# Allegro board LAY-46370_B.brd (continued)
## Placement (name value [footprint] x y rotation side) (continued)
R328  22  [0402_CC]  15.29 10.84 90 top
R329  10K  [0402_CC]  16.83 13.45 90 top
R330  12K  [0402_CC]  12.22 13.11 270 top
R333  1.5K  [0402_CC]  21.49 21.94 180 top
R334  1.5K  [0402_CC]  21.49 23.5 180 top
R347  10K  [0402_CC]  6.98 52.18 90 bottom
R351  10K  [0402_CC]  24.01 67.24 180 bottom
R363  0  [0402_CC]  7.02 64.89 0 bottom
R364  0  [0402_CC]  7.02 65.98 0 bottom
R369  0  [0402_CC]  156.01 86.88 270 bottom
R370  0  [0402_CC]  154.92 86.88 270 bottom
R371  0  [0402_CC]  153.83 86.88 270 bottom
R372  0  [0402_CC]  152.74 86.88 270 bottom
R373  1K  [0402_CC]  163.3 83.55 270 bottom
R374  1K  [0402_CC]  160.87 83.48 270 bottom
R381  1K  [0402_CC]  21.33 52.93 90 bottom
R382  0  [0402_CC]  22.3 47.06 180 bottom
R383  10K  [0402_CC]  22.31 48.23 180 bottom
R385  10K  [0402_CC]  19.25 52.94 90 bottom
R386  100  [0402_CC]  9.13 73.62 90 bottom
R387  100  [0402_CC]  10.23 73.63 90 bottom
R388  100  [0402_CC]  11.34 73.63 90 bottom
R389  100  [0402_CC]  12.47 73.63 90 bottom
R390  100  [0402_CC]  13.57 73.61 90 bottom
R391  100  [0402_CC]  14.66 73.6 90 bottom
R392  100  [0402_CC]  15.76 73.6 90 bottom
R393  100  [0402_CC]  15.97 71.96 0 bottom
R394  100  [0402_CC]  15.97 70.87 0 bottom
R395  100  [0402_CC]  15.97 69.76 0 bottom
R396  100  [0402_CC]  15.98 67.55 0 bottom
R397  100  [0402_CC]  15.19 64.62 270 bottom
R398  100  [0402_CC]  14.11 64.62 270 bottom
R399  100  [0402_CC]  10.85 64.62 270 bottom
R400  100  [0402_CC]  9.76 64.62 270 bottom
R401  100  [0402_CC]  33.96 65.57 270 top
R406  0  [0402_CC]  12.31 133.65 270 top
R407  0  [0402_CC]  177.98 87.32 0 top
R408  0  [0402_CC]  21.02 68.92 270 bottom
R409  10K  [0402_CC]  22.15 68.92 270 bottom
R410  10K  [0402_CC]  19.92 68.9 270 bottom
R411  10K  [0402_CC]  8.06 73.62 270 bottom
R412  0  [0402_CC]  6.97 73.61 270 bottom
R413  10K  [0402_CC]  7.05 69.46 0 bottom
R415  10K  [0402_CC]  15.97 68.65 180 bottom
R416  10K  [0402_CC]  15.97 66.46 180 bottom
R417  10K  [0402_CC]  16.27 64.62 90 bottom
R418  10K  [0402_CC]  13.02 64.62 90 bottom
R419  10K  [0402_CC]  11.94 64.62 90 bottom
R420  10K  [0402_CC]  8.67 64.62 90 bottom
R421  10K  [0402_CC]  35.11 65.55 90 top
R422  0  [RC0402_25]  151.67 86.88 270 bottom
R423  0  [RC0402_25]  150.69 86.88 270 bottom
R424  0  [RC0402_25]  87.96 24.57 0 top
R425  0  [RC0402_25]  87.96 26.67 0 top
R426  10K  [0402_CC]  130.5 23.86 90 top
R427  10K  [0402_CC]  13.15 79.47 0 bottom
R429  10K  [0402_CC]  15.01 39.13 270 top
R430  10K  [0402_CC]  13.92 39.13 270 top
R431  10K  [0402_CC]  18.88 31.7 90 top
R435  0  [0402_CC]  13.38 33.02 90 top
R436  0  [RC0402_25]  23.93 73.29 90 bottom
R437  0  [RC0402_25]  22.82 73.28 90 bottom
R438  4.7K  [0402_CC]  91.16 34.32 90 top
R439  4.7K  [0402_CC]  78.08 36.58 270 top
R440  0  [0402_CC]  25.21 54.29 270 bottom
R441  0  [0402_CC]  29.68 47.3 90 bottom
R442  0  [0402_CC]  28.61 47.29 90 bottom
R443  0  [0402_CC]  27.55 47.29 90 bottom
R444  10K  [0402_CC]  178.79 85.29 180 top
R445  10K  [0402_CC]  178.78 84.2 180 top
R446  0  [0402_CC]  19.03 102.2 180 bottom
R447  10K  [0402_CC]  28.77 18.2 180 top
R448  10K  [0402_CC]  56.68 25.49 270 top
R449  0  [0402_CC]  5.4 67.63 90 bottom
R450  100K  [0402_CC]  17.38 98.34 180 bottom
R451  22K  [0402_CC]  126.63 80.1 0 bottom
R452  0  [0402_CC]  133.13 76.2 0 bottom
R453  47K  [0603_CC]  32.32 15.15 180 bottom
R455  10K  [0402_CC]  176.71 125.54 0 top
R456  0  [0402_CC]  179.78 119.73 180 top
R457  10K  [0402_CC]  179.78 120.89 0 top
R458  0  [RC0402_25]  19.86 75.08 270 bottom
SW1  SPST PB  [SW4_PB_ESW_SM_P177]  193.16 145.98 180 top
SW2  SPST PB  [SW4_PB_ESW_SM_P177]  180.17 146 180 top
SW3  M096H-A020RT21A  [SW6_DPDT_M096H_TH]  19.56 145.1 180 top
SW4  DHN-04  [97C04]  7.01 130 0 top
TP1  TP_35MIL  [TESTPOINT_35MIL]  110.23 116.55 0 top
TP2  TP_35MIL  [TESTPOINT_35MIL]  111.75 116.55 0 top
TP3  TP_35MIL  [TESTPOINT_35MIL]  113.28 116.55 0 top
TP4  TP_35MIL  [TESTPOINT_35MIL]  114.8 116.55 0 top
TP5  TP_35MIL  [TESTPOINT_35MIL]  174.53 102.7 0 top
TP6  TP_35MIL  [TESTPOINT_35MIL]  174.53 101.31 0 top
TP7  TP_35MIL  [TESTPOINT_35MIL]  174.53 99.91 0 top
TP8  TP_35MIL  [TESTPOINT_35MIL]  174.53 98.51 0 top
TP9  TP_35MIL  [TESTPOINT_35MIL]  111.21 87.09 270 bottom
TP10  TP_35MIL  [TESTPOINT_35MIL]  108.59 87.05 270 bottom
TP11  TP_35MIL  [TESTPOINT_35MIL]  113.01 84.15 90 bottom
TP12  TP_35MIL  [TESTPOINT_35MIL]  110.07 82.45 90 bottom
TP13  -  [TPAD_020]  25.51 27.47 90 top
TP14  -  [TPAD_020]  29.71 10.02 90 top
TP15  -  [TPAD_020]  35.81 3.52 0 top
TP16  -  [TPAD_020]  27.24 14.8 270 top
TP17  -  [TPAD_020]  33.23 15.23 180 top
TP18  -  [TPAD_020]  28.77 21.03 180 top
TP19  -  [TPAD_020]  28.73 14.8 180 top
TP20  -  [TPAD_020]  33.35 21.49 180 top
TP21  -  [TPAD_020]  29.98 14.8 180 top
TP22  TP_35MIL  [TESTPOINT_35MIL]  28.78 19.61 180 top
TP23  TP_35MIL  [TESTPOINT_35MIL]  45.14 22.22 270 top
TP24  -  [TPAD_020]  45.88 9.5 0 top
TP25  -  [TPAD_020]  38.29 3.52 0 top
TP26  -  [TPAD_020]  42.74 14.43 0 top
TP27  -  [TPAD_020]  43.45 29.44 180 top
TP28  -  [TPAD_020]  41.7 24.4 180 top
TP29  -  [TPAD_020]  45.74 29.44 180 top
TP30  -  [TPAD_020]  43.51 24.39 180 top
TP31  TP_35MIL  [TESTPOINT_35MIL]  41.91 28.81 180 top
TP32  TP_35MIL  [TESTPOINT_35MIL]  109.75 34.02 0 top
TP33  -  [TPAD_020]  97.23 29.24 0 top
TP34  TP_35MIL  [TESTPOINT_35MIL]  77.44 38.25 0 top
TP35  -  [TPAD_020]  78.26 28.56 0 top
TP36  -  [TPAD_020]  163.92 110.15 180 top
TP37  -  [TPAD_020]  163.54 99.61 0 top
TP38  -  [TPAD_020]  162.5 99.59 0 top
TP39  -  [TPAD_020]  150.57 89.82 0 top
TP40  -  [TPAD_020]  149.2 127.96 0 top
TP41  -  [TPAD_050]  178.76 130.83 0 top
TP42  TP_35MIL  [TESTPOINT_35MIL]  105.98 66.72 90 bottom
TP43  -  [TPAD_050]  62.94 135.12 180 bottom
TP44  -  [TPAD_050]  86.25 135.09 180 bottom
TP45  -  [TPAD_020]  78.38 114.89 270 top
TP46  -  [TPAD_020]  79.69 114.88 0 top
TP47  -  [TPAD_050]  38.56 134.87 180 bottom
TP48  -  [TPAD_020]  36.51 134.83 180 bottom
TP49  -  [TPAD_020]  133.2 132.3 180 bottom
TP50  -  [TPAD_020]  108.88 132.77 180 bottom
TP51  -  [TPAD_020]  192.98 26.2 180 top
TP52  -  [TPAD_020]  98.45 54.15 0 top
TP53  -  [TPAD_020]  99.72 54.15 0 top
TP54  -  [TPAD_020]  101 54.15 0 top
TP55  -  [TPAD_020]  102.27 54.15 0 top
TP56  TP_35MIL  [TESTPOINT_35MIL]  104.1 66.73 270 bottom
TP57  TP_35MIL  [TESTPOINT_35MIL]  13.38 41.07 0 top
TP58  TP_35MIL  [TESTPOINT_35MIL]  10.33 41.07 0 top
TP60  TP_35MIL  [TESTPOINT_35MIL]  11.86 41.07 0 top
TP61  TP_35MIL  [TESTPOINT_35MIL]  8.81 41.07 0 top
TP62  -  [TPAD_020]  117.67 79.67 0 top
TP67  -  [TPAD_050]  181.98 112.14 180 top
TP68  -  [TPAD_050]  188.84 112.14 180 top
TP69  TP_35MIL  [TESTPOINT_35MIL]  46.64 65.74 180 bottom
TP70  -  [TPAD_050]  185.41 112.14 0 top
TP71  TP_35MIL  [TESTPOINT_35MIL]  45.09 104.46 270 bottom
TP72  TESTLOOP  [TEST_PIN_TP107]  150.09 20.63 0 top
TP73  TESTLOOP  [TEST_PIN_TP107]  38.66 37.74 0 top
TP74  TESTLOOP  [TEST_PIN_TP107]  7.12 88.3 180 bottom
TP75  -  [TPAD_050]  175.7 130.77 0 top
TP76  -  [TPAD_050]  107.66 116.51 0 top
TP77  -  [TPAD_050]  176.84 52.98 0 top
TP78  -  [TPAD_050]  113.06 24.42 0 top
TP79  -  [TPAD_050]  116.78 116.6 0 top
TP80  -  [TPAD_050]  93.56 40.6 0 top
TP81  TP_35MIL  [TESTPOINT_35MIL]  19.03 100.94 0 bottom
TP82  TP_35MIL  [TESTPOINT_35MIL]  125.64 58.12 180 top
TP83  TP_35MIL  [TESTPOINT_35MIL]  125.64 59.64 180 top
TP84  TP_35MIL  [TESTPOINT_35MIL]  125.64 61.17 180 top
TP85  TP_35MIL  [TESTPOINT_35MIL]  125.64 56.59 180 top
TP86  TP_35MIL  [TESTPOINT_35MIL]  178.69 50.8 0 top
TP87  -  [TPAD_020]  159.86 133.1 0 top
TP88  -  [TPAD_020]  161.21 133.12 0 top
TP89  TP_35MIL  [TESTPOINT_35MIL]  161.61 127.94 0 top
TP90  TP_35MIL  [TESTPOINT_35MIL]  161.84 123.78 0 top
TP93  -  [TPAD_020]  4.77 20.93 0 top
TP94  -  [TPAD_020]  160.02 135.95 0 top
TP95  -  [TPAD_020]  161.29 135.95 0 top
TP96  -  [TPAD_020]  21.29 70.25 180 bottom
TP97  -  [TPAD_020]  33.61 16.2 0 top
TP98  -  [TPAD_020]  152.78 95.91 0 top
TP99  TP_35MIL  [TESTPOINT_35MIL]  138.8 86.68 90 top
TP100  TP_35MIL  [TESTPOINT_35MIL]  138.8 85.28 90 top
TP101  TP_35MIL  [TESTPOINT_35MIL]  138.8 83.88 90 top
TP102  -  [TPAD_050]  32.71 30.09 0 top
TP103  TP_35MIL  [TESTPOINT_35MIL]  55.95 18.08 0 top
TP104  TP_35MIL  [TESTPOINT_35MIL]  143.56 87.2 0 top
TP105  -  [TPAD_050]  23.54 121.92 0 top
TP106  TP_35MIL  [TESTPOINT_35MIL]  133.88 41.44 0 top
TP107  TP_35MIL  [TESTPOINT_35MIL]  130.07 41.44 0 top
TP108  TP_35MIL  [TESTPOINT_35MIL]  131.98 41.44 0 top
TP109  TP_35MIL  [TESTPOINT_35MIL]  128.17 41.44 0 top
TP110  -  [TPAD_050]  56.55 35.57 0 top
TP111  TP_35MIL  [TESTPOINT_35MIL]  44.33 126.03 0 top
TP112  TP_35MIL  [TESTPOINT_35MIL]  68.3 126.1 0 top
TP113  TP_35MIL  [TESTPOINT_35MIL]  92.24 126.03 0 top
TP114  TP_35MIL  [TESTPOINT_35MIL]  116.35 126.09 0 top
TP115  TP_35MIL  [TESTPOINT_35MIL]  140.35 126.03 0 top
TP116  TP_35MIL  [TESTPOINT_35MIL]  157.32 84.47 0 top
TP117  TP_35MIL  [TESTPOINT_35MIL]  155.42 84.47 0 top
TP118  TP_35MIL  [TESTPOINT_35MIL]  153.51 84.47 0 top
TP119  TP_35MIL  [TESTPOINT_35MIL]  151.61 84.47 0 top
TP120  -  [TPAD_050]  197.95 138.42 0 top
TP121  -  [TPAD_050]  96.5 54.2 0 top
TP122  -  [TPAD_050]  84.17 115.48 0 top
TP123  -  [TPAD_050]  86.21 115.48 0 top
TP124  -  [TPAD_020]  20.71 35 0 top
TP125  TP_35MIL  [TESTPOINT_35MIL]  172.27 123.23 0 top
TP126  TP_35MIL  [TESTPOINT_35MIL]  24.81 47.68 270 bottom
TP127  TP_35MIL  [TESTPOINT_35MIL]  22.65 64.38 270 bottom
TP128  -  [TPAD_020]  159.06 105.29 0 top
TP129  TP_35MIL  [TESTPOINT_35MIL]  28.32 41.19 0 top
TP130  TP_35MIL  [TESTPOINT_35MIL]  29.97 41.19 0 top
TP131  TP_35MIL  [TESTPOINT_35MIL]  91.05 54.24 0 top
TP132  TP_35MIL  [TESTPOINT_35MIL]  92.7 54.24 0 top
TP133  -  [TPAD_020]  21.12 19.07 0 top
TP134  -  [TPAD_020]  23.55 69.28 180 bottom
TVS1  ESD5B5.0ST1G  [DIODE2_SOD523]  175.69 133.5 90 bottom
TVS2  ESD5B5.0ST1G  [DIODE2_SOD523]  180.36 133.47 90 bottom
TVS3  ESD5B5.0ST1G  [DIODE2_SOD523]  198.94 15.52 270 top
TVS4  ESD5B5.0ST1G  [DIODE2_SOD523]  190.02 15.58 270 top
TVS5  ESD5B5.0ST1G  [DIODE2_SOD523]  192.92 15.6 270 top
TVS6  ESD5B5.0ST1G  [DIODE2_SOD523]  196.03 15.5 270 top
TVS7  ESD5B5.0ST1G  [DIODE2_SOD523]  12.04 7.95 270 top
TVS8  ESD5B5.0ST1G  [DIODE2_SOD523]  35.19 70.1 270 bottom
U1  PCA6416AHF,128  [QFN24_4X4_EP2P25MM]  182.4 85.22 270 top
U2  74LVC1G125GM  [UDFN6_1X1P5MM]  177.94 89.02 0 top
U3  74AVC8T245BQ  [QFN24_0P5_5P6X3P6_EP]  133.74 86.18 0 bottom
U4  74AVC4T245GU  [XQFN16_0P4_2P7X1P9]  117.93 32.38 0 top
U5  NTS0104GU12  [XQFN12_0P4_1P8X2P1]  179.92 101.29 0 top
U6  NTS0104GU12  [XQFN12_0P4_1P8X2P1]  111.63 93.75 270 bottom
U7  74AVC4T3144  [XQFN12_0P4_1P8X2P1]  14.11 49.14 180 bottom
U8  TMUX1574RSVR  [PQFN16_0P4_2P65X1P85]  8.23 49.37 270 bottom
U9  NX20P5090UK  [WLCSP15_0P5_1P57X2P59]  29.59 25.19 90 top
U10  NX20P0407  [WLCSP12_0P4_1P3X1P7MM_SMDP]  26.01 12.34 90 top
U11  PTN5110  [HX2QFN16_0P4_2P7X2P7]  32.19 18.32 180 top
U12  SGM8709YN5G  [SOT-23-5]  68.36 36.75 0 top
U13  TPS70933DBVR  [SOT23-5]  42.48 19.69 270 top
U14  NX20P3483UK  [WLCSP42_0P4_2P94X2P54_SMDP]  59.13 33.95 180 top
U15  NX20P0407  [WLCSP12_0P4_1P3X1P7MM_SMDP]  41.94 12.39 90 top
U16  PCMF2USB3S  [WLCSP10_0P4_1P2X1P6MM_SMDP]  46.43 12.43 270 top
U17  PTN5110  [HX2QFN16_0P4_2P7X2P7]  44.87 26.73 180 top
U18  CBTU02043  [HUQFN16_1P6X2P4]  49.32 17.05 270 top
U19  PCMF2USB3S  [WLCSP10_0P4_1P2X1P6MM_SMDP]  49.4 12.38 270 top
U20  TMUX1574RSVR  [PQFN16_0P4_2P65X1P85]  9.77 78.17 180 bottom
U21  PCMF2USB3S  [WLCSP10_0P4_1P2X1P6MM_SMDP]  67.66 20.61 270 top
U22  NX5P3363UKZ  [BGA16_0P5_2P23X2P23]  59.08 22.75 90 top
U23  RTL8211FDI-CG  [QFN40_0P4_5X5MM]  101.62 28.66 90 top
U24  IP4292CZ10-TBR  [XSON10_0P5_1P1X2P6MM]  104.82 19.96 90 top
U25  IP4292CZ10-TBR  [XSON10_0P5_1P1X2P6MM]  100.81 19.96 90 top
U26  RTL8211FDI-CG  [QFN40_0P4_5X5MM]  82.56 28.69 90 top
U27  IP4292CZ10-TBR  [XSON10_0P5_1P1X2P6MM]  84.46 19.96 90 top
U28  IP4292CZ10-TBR  [XSON10_0P5_1P1X2P6MM]  80.43 19.96 90 top
U29  9FGV0241AKLF  [QFN24_0P5_4X4_EP2P2]  159.95 109.84 180 top
U30  PCMF1HDMI2S  [WLCSP5_0P4_0P82X1P22]  160.33 137.56 0 top
U31  IP4292CZ10-TBR  [XSON10_0P5_1P1X2P6MM]  70.86 126.08 90 top
U32  IP4292CZ10-TBR  [XSON10_0P5_1P1X2P6MM]  65.77 126.08 270 top
U33  IP4292CZ10-TBR  [XSON10_0P5_1P1X2P6MM]  57.14 126.08 270 top
U34  IP4292CZ10-TBR  [XSON10_0P5_1P1X2P6MM]  94.73 126.08 90 top
U35  IP4292CZ10-TBR  [XSON10_0P5_1P1X2P6MM]  89.71 126.08 270 top
U36  IP4292CZ10-TBR  [XSON10_0P5_1P1X2P6MM]  80.8 126.08 270 top
U37  IP4292CZ10-TBR  [XSON10_0P5_1P1X2P6MM]  41.87 126.08 270 top
U38  IP4292CZ10-TBR  [XSON10_0P5_1P1X2P6MM]  46.82 126.08 90 top
U39  IP4292CZ10-TBR  [XSON10_0P5_1P1X2P6MM]  32.61 126.08 270 top
U40  IP4292CZ10-TBR  [XSON10_0P5_1P1X2P6MM]  142.89 126.08 90 top
U41  IP4292CZ10-TBR  [XSON10_0P5_1P1X2P6MM]  137.84 126.08 270 top
U42  IP4292CZ10-TBR  [XSON10_0P5_1P1X2P6MM]  129.09 126.08 270 top
U43  IP4292CZ10-TBR  [XSON10_0P5_1P1X2P6MM]  118.87 126.08 90 top
U44  IP4292CZ10-TBR  [XSON10_0P5_1P1X2P6MM]  113.72 126.08 270 top
U45  IP4292CZ10-TBR  [XSON10_0P5_1P1X2P6MM]  105.25 126.08 270 top
U46  PCMF2HDMI2S  [WLCSP10_0P4_1P2X1P6MM_SMDP]  158.08 137.55 90 top
U47  PCMF2HDMI2S  [WLCSP10_0P4_1P2X1P6MM_SMDP]  155.68 137.56 90 top
U48  PCA9509ADP  [TSSOP8_A]  167.74 126.22 0 top
U49  MP2263GD  [DFN15_0P4_2X3]  22.83 99.31 90 bottom
U50  WM8960  [QFN32_S142EP]  191.96 30.07 180 top
U51  TJA1048T  [SOIC14_1P27_4X8]  134.6 28.89 270 top
U52  NLAS3158  [WDFN12_0P5_3X1MM]  110.32 84.52 90 bottom
U53  74AVC4T245GU  [XQFN16_0P4_2P7X1P9]  134.94 37.94 90 top
U54  NLAS3158  [WDFN12_0P5_3X1MM]  130.81 57.54 90 top
U55  NTB0104GU12  [XQFN12_0P4_1P8X2P1]  182.59 75.77 0 top
U56  NTS0104GU12  [XQFN12_0P4_1P8X2P1]  182.64 93.69 0 top
U57  NTB0104GU12  [XQFN12_0P4_1P8X2P1]  182.42 58.01 0 top
U58  NTB0104GU12  [XQFN12_0P4_1P8X2P1]  182.45 49.49 0 top
U59  RT9193  [SOT23-5]  3.9 13.08 0 top
U60  FT4232H  [LQFP64_0P5_10X10]  13.02 21.45 90 top
U61  74AVC4T245GU  [XQFN16_0P4_2P7X1P9]  12.4 36.47 90 top
U62  PCMF1USB3S  [WLCSP5_0P4_0P82X1P22]  14.74 8.67 180 top
U63  MP8759GD  [QFN12_0P5_3P1X2P1]  42.91 64.79 180 bottom
U64  MP2147GD  [QFN12_0P5_2X3MM_EP]  41.65 106.61 270 bottom
U66  74AUP1G126GM  [UDFN6_1X1P5MM]  21.21 73.16 270 bottom
U67  74AUP1G126GM  [UDFN6_1X1P5MM]  21.78 66.58 270 bottom
U70  PCA6416AHF,128  [QFN24_4X4_EP2P25MM]  11.41 69.07 0 bottom
U71  AP2331SA-7  [SOT-23]  171.09 138.23 270 top
U74  RT9193-18GB  [SOT23-5]  5.14 31.12 0 top
U75  PCMF1USB3S  [WLCSP5_0P4_0P82X1P22]  44.36 12.43 180 top
U77  PCMF1USB3S  [WLCSP5_0P4_0P82X1P22]  65.44 20.6 180 top
U78  74LVC1G04GM  [UDFN6_1X1P5MM]  17.25 31.71 90 top
U79  74LVC1G125GM  [UDFN6_1X1P5MM]  162.32 130.77 270 top
U80  AT24C16C  [TSSOP8]  27.87 52.5 270 bottom
U81  74LVC1G125GM  [UDFN6_1X1P5MM]  155.91 103.28 180 top
X1  12 MHz  [XTAL_4_3P3X2P6MM]  8.31 11.23 0 top
Y1  25MHz  [XTLOSC4_2P5X2MM_SM]  94.97 26.73 270 top
Y2  25MHz  [XTLOSC4_2P5X2MM_SM]  75.75 25.42 270 top
Y3  25MHz  [XTLOSC4_2P5X2MM_SM]  166.46 108.29 90 top

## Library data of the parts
BH1-BH4 BH9-BH12 = MOUNT_HOLE
BH5-BH8 = SPACER
C1 C3 C6 C8 C14 C34 C48 C50 C52 C53 C55 C68 C75 C84 C87 C94 C104 C168 C223 C238 C263 C277 C283 C286 C288 C305 C307 C309 C317 C319 C321 C324 C328 C330 C333 C334 = CAP_NP: tolerance: 10%
C2 C4 C5 C7 C9-C13 C15-C24 C27 C29-C33 C35-C37 C42-C47 C51 C54 C56 C57 C59 C60 C64-C67 C69-C74 C76-C78 C85 C86 C88-C93 C95 C96 C112 C115 C123-C137 C139 C140 C143 C144 C147-C150 C152-C158 C161-C164 C169-C171 C174-C179 C181-C200 C224 C226 C228-C237 C239-C246 C251 C254 C256-C261 C264-C267 C269 C271-C276 C278 C280 C287 C289 C294-C300 C306 C308 C310 C318 C320 C322 C325-C327 C329 C331 C332 C335-C343 C345 C346 C348 C349 = CAP_NP
C25 C26 C40 C146 C151 C255 C279 C281 C282 = CAP_POL
C41 C61 C62 C270 = MOT_CAP
C79-C83 C97-C100 = CAP_NP: room: RGMII_PHY
C101 = CAP_NP: room: RGMII_PHY; signal model: DEFAULT_CAPACITOR_2.2e+07pF_2_1
C102 = CAP_NP: tolerance: 10%; signal model: DEFAULT_CAPACITOR_220000pF_2_1
C103 C107-C109 C217 = CAP_NP: tolerance: 10%; signal model: DEFAULT_CAPACITOR_2.2e+07pF_2_1
C105 C106 C219 = CAP_NP: tolerance: 10%; signal model: DEFAULT_CAPACITOR_100000pF_2_1
C110 C111 = CAP_NP: room: ATLAS-AP
C113 C116 C117 C121 C145 C215 C216 C220 = CAP_NP: signal model: DEFAULT_CAPACITOR_100000pF_2_1
C114 C141 C201 C202 C205 C207 = CAP_NP: signal model: DEFAULT_CAPACITOR_1e+06pF_2_1
C118 = CAP_NP: signal model: DEFAULT_CAPACITOR_1000pF_2_1
C119 C120 C142 C214 C218 = CAP_NP: signal model: DEFAULT_CAPACITOR_2.2e+07pF_2_1
C138 = CAP_NP: signal model: DEFAULT_CAPACITOR_220000pF_2_1
C203 C204 = CAP_NP: tolerance: 10%; signal model: DEFAULT_CAPACITOR_10000pF_2_1
C206 C208 = CAP_NP: signal model: DEFAULT_CAPACITOR_10000pF_2_1
C252 C253 = CAP_NP: tolerance: 5%; room: RGMII_PHY
CON1 = CONN_HDR_4X1
D2 D4 D9 D32 = DIODE
D5 D6 D22 D23 D26 = DIODE_SCHTKY
D10-D13 TVS1-TVS8 = DIODE_TVS_BIDIR
D14 D15 = ESD_DIODE_2LINE
D16 D17 D20 D21 D25 D30 D31 = LED
D24 = ZDIODE
F1 F2 = FUSE
J1-J4 = HDR_2X50_M
J5 J6 = USB24_TYPEC_SH4
J7 = USB_3P0_Standard-A
J8 J9 = RJ45_2 DUAL_LED_10P
J10 = CON_67_FEMALE_RA_A
J11 = CONN_MICRO_SDCARD_9P
J12-J16 = CON_2X18_SH6
J17 = ATOM010130010052_HDMI_19P
J18 = CON_KJ366EYS_AUDIOJACK_6P
J19 J20 = CONN_DB9F_MTGTABS
J21 = CONN_HDR_20X2
J22 = CONN_HDR_4X2
J23 = USB_MINI_B_SKT
J24 = CONN_HDR_5X2
J25 = HDR_2X20_M
J26 = CONN_HDR_3X1
J27 = CONN_HDR_2X1
L1-L15 L21-L24 = INDUCTOR_FERRITE
L16 L18 = INDUCTOR
L17 = INDUCTOR: tolerance: 20%
L19 L20 = DLW43
L25 L26 = BEAD_0
Q1 Q2 Q5 Q7 Q10-Q13 Q15 Q17 = NX3008NBKW_SOT323
Q6 Q16 = MOSFET_P
Q8 Q14 = MOSFET_P_5P_SO8
R1 R2 R4 R5 R7-R47 R49-R65 R67 R68 R70 R74 R78 R81-R84 R86-R99 R104 R116-R119 R121-R124 R126-R128 R130 R132 R141 R142 R144 R147-R149 R152-R181 R183 R185-R200 R216-R218 R221-R226 R230-R233 R235-R238 R240-R246 R251-R254 R256 R258-R261 R263-R273 R276 R278 R280-R310 R312-R315 R317 R318 R322 R323 R329 R333 R334 R347 R351 R363 R364 R369-R374 R383 R385-R401 R407-R413 R415-R423 R426 R427 R429-R431 R435 R436 R438-R453 R456 R458 = RES
R48 R66 R71-R73 R75-R77 R79 R80 R106 R381 R424 R425 R455 R457 = RES: tolerance: 5%
R85 R100 = RES: room: RGMII_PHY
R101 R137 = RES: signal model: DEFAULT_RESISTOR_0.0015OHM_2_1
R102 = RES: tolerance: 5%; signal model: DEFAULT_RESISTOR_3.300000OHM_2_1
R103 = RES: tolerance: 5%; signal model: DEFAULT_RESISTOR_0.001OHM_2_1
R105 = RES: tolerance: 5%; signal model: DEFAULT_RESISTOR_44200OHM_2_1
R107 R108 = RES: tolerance: 5%; signal model: DEFAULT_RESISTOR_100000OHM_2_1
R109 = RES: signal model: DEFAULT_RESISTOR_9530OHM_2_1
R110 = RES: tolerance: 5%; signal model: DEFAULT_RESISTOR_187000OHM_2_1
R111 = RES: tolerance: 5%; signal model: DEFAULT_RESISTOR_41200OHM_2_1
R112 R113 R115 R133 R215 = RES: signal model: DEFAULT_RESISTOR_100000OHM_2_1
R114 R131 R134 = RES: signal model: DEFAULT_RESISTOR_1000.000000OHM_2_1
R120 R140 R210-R212 = RES: signal model: DEFAULT_RESISTOR_0.001OHM_2_1
R125 = RES: signal model: DEFAULT_RESISTOR_22000OHM_2_1
R129 = RES: signal model: DEFAULT_RESISTOR_4700OHM_2_1
R135 = RES: signal model: DEFAULT_RESISTOR_499000OHM_2_1
R136 = RES: signal model: DEFAULT_RESISTOR_499.000000OHM_2_1
R138 = RES: signal model: DEFAULT_RESISTOR_0.0012OHM_2_1
R139 = RES: signal model: DEFAULT_RESISTOR_118000OHM_2_1
R201-R204 R206-R209 R214 = RES: signal model: DEFAULT_RESISTOR_10000OHM_2_1
R205 = RES: tolerance: 5%; signal model: DEFAULT_RESISTOR_10000OHM_2_1
R247 R248 R327 R328 R330 R382 R406 R437 = RES: tolerance: 1%
SW1 SW2 = SW_PB_ESW
SW3 = SW_DPDT_3
SW4 = SW_DIP-4_SM
TP1-TP12 TP22 TP23 TP31 TP32 TP34 TP42 TP56-TP58 TP60 TP61 TP69 TP71 TP81-TP86 TP89 TP90 TP99-TP101 TP103 TP104 TP106-TP109 TP111-TP119 TP125-TP127 TP129-TP132 = T POINT R: Tolerance: TOLERANCE; User Part Number: 510-75618
TP13-TP21 TP24-TP30 TP33 TP35-TP41 TP43-TP55 TP62 TP67 TP68 TP70 TP72-TP80 TP87 TP88 TP93-TP98 TP102 TP105 TP110 TP120-TP124 TP128 TP133 TP134 = TESTLOOP
U1 U70 = PCAL6416AHF_QFN24
U2 U79 U81 = 74AUP1G125GN_6P
U3 = SN74AVC8T245
U4 U53 U61 = 74AVC4T245GU_XQFN16
U5 U6 U56 = NTS0104GU12_12P
U7 = 74AVC4T3144_12P
U8 U20 = TMUX1574RSVR
U9 = NX20P5090UK
U10 U15 = NX20P0407_WLCSP12_A
U11 U17 = PTN5110_QFN16
U12 = SGM8709YN5G
U13 = TPS709_1
U14 = NX20P3483UK_42P
U16 U19 U21 U46 U47 = PCMF2USB3S_10P
U18 = CBTU02043HEJ_17P
U22 = NX5P3290_WLCSP16
U23 U26 = RTL8211FD-40P
U24 U25 U27 U28 U31-U45 = PUSB3F96_DFN2510A_10P
U29 = 9FGV0241AKLF_24P
U30 U75 U77 = PESD1USB30_A
U48 = PCA9509ADP
U49 = MP2263GD_DFN15_A
U50 = WM8960_QFN_33P
U51 = TJA1048T_SO_14P
U52 U54 = NLAS3158
U55 U57 U58 = NTB0104GU12_12P
U59 U74 = RT9193-33PB
U60 = FT4232HL_LQFP64
U62 = PCMF1USB3S_WLCSP5
U63 = MP8759GD_QFN12P
U64 = MP2147GD_QFN_11P
U66 U67 = 74AUP1G126GM
U71 = AP2331SA
U78 = NC7SV04
U80 = AT24C16C_8P
X1 = XTAL_13
Y1-Y3 = XTAL_13Y

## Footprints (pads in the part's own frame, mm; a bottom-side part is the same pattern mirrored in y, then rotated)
97C04
  rect 0.762x1.245 smd: 1(-1.905,-3.073) 2(-0.635,-3.073) 3(0.635,-3.073) 4(1.905,-3.073) 5(1.905,3.073) 6(0.635,3.073) 7(-0.635,3.073) 8(-1.905,3.073)
0402_CC
  rect 0.457x0.508 smd: 1(-0.375,0) 2(0.375,0)
0603_CC
  rect 0.711x0.838 smd: 1(-0.65,0) 2(0.65,0)
0805_CC
  rect 0.94x1.346 smd: 1(-0.78,0) 2(0.78,0)
1206_CC
  rect 0.94x1.702 smd: 1(-1.4,0) 2(1.4,0)
1210_CC
  rect 0.94x2.591 smd: 1(-1.4,0) 2(1.4,0)
BGA16_0P5_2P23X2P23
  round 0.254 smd: A1(-0.75,0.75) A2(-0.25,0.75) A3(0.25,0.75) A4(0.75,0.75) B1(-0.75,0.25) B2(-0.25,0.25) B3(0.25,0.25) B4(0.75,0.25) C1(-0.75,-0.25) C2(-0.25,-0.25) C3(0.25,-0.25) C4(0.75,-0.25) D1(-0.75,-0.75) D2(-0.25,-0.75) D3(0.25,-0.75) D4(0.75,-0.75)
CC0603
  rect 0.991x0.813 smd: 1(-0.686,0) 2(0.686,0)
CC1210
  rect 1.778x2.845 smd: 1(-1.397,0) 2(1.397,0)
CCE6P8X6P8
  rect 3.556x1.651 smd: 1(-2.35,0) 2(2.35,0)
CCE8P3X8P3
  rect 4.394x1.905 smd: 1(-2.807,0) 2(2.807,0)
CON2X18_RECEP_WSHELL_0P8_SM_RA
  round 0.254 hole 1.549 unplated: (-8,3.975) (8,3.975)
  round 1.092 hole 0.813: 1(-8.9,-1.745) 2(8.9,-1.745) 3(-8.9,-5.245) 4(8.9,-5.245) 5(-8.9,-7.245) 6(8.9,-8.245)
  oval 0.356x1.778 smd: A1(-6.6,9.155) A2(-5.8,9.155) A3(-5,9.155) A4(-4.2,9.155) A5(-3.4,9.155) A6(-2.6,9.155) A7(-1.8,9.155) A8(-1,9.155) A9(-0.2,9.155) A10(0.6,9.155) A11(1.4,9.155) A12(2.2,9.155) A13(3,9.155) A14(3.8,9.155) A15(4.6,9.155) A16(5.4,9.155) A17(6.2,9.155) A18(7,9.155) B1(-7,11.665) B2(-6.2,11.665) B3(-5.4,11.665) B4(-4.6,11.665) B5(-3.8,11.665) B6(-3,11.665) B7(-2.2,11.665) B8(-1.4,11.665) B9(-0.6,11.665) B10(0.2,11.665) B11(1,11.665) B12(1.8,11.665) B13(2.6,11.665) B14(3.4,11.665) B15(4.2,11.665) B16(5,11.665) B17(5.8,11.665) B18(6.6,11.665)
CON6_AUDIOJACK_RA_TH
  round 0.254 hole 1.499 unplated: (0.4,2.7) (7.4,2.7)
  oval 2.108x1.092 hole 1.499x0.508: 1(0,0) 2(0,5.15)
  rect 1.6x1.803 smd: 3(9.4,-0.8) 4(9.4,6.2) 5(6.2,6.2) 6(6.2,-0.8)
CON9_SDCARD_1P1MM
  round 0.254 hole 0.991 unplated: (-4.95,-3.25) (3.05,-3.25)
  rect 0.711x1.6 smd: 1(2.25,7.25) 2(1.15,7.25) 3(0.05,7.25) 4(-1.05,7.25) 5(-2.15,7.25) 6(-3.25,7.25) 7(-4.35,7.25) 8(-5.45,7.25) 9(-6.55,7.25)
  rect 1.194x1.6 smd: 10(-7.75,6.65)
  rect 1.194x2.21 smd: 11(-7.75,-2.85) 12(7.75,-2.85)
  rect 1.6x1.397 smd: 13(6.85,6.75)
CON9_USB_16P8X14P2_TH
  rect 1.219x1.219 hole 0.711: 1(0,0)
  round 1.219 hole 0.711: 2(0,-2.5) 3(0,-4.5) 4(0,-7) 5(1.5,-7.5) 6(1.5,-5.5) 7(1.5,-3.5) 8(1.5,-1.5) 9(1.5,0.5)
  round 2.946 hole 2.311: S1(-2,3.07) S2(-2,-10.07)
CON24_USB_TYPEC_RA_SMT_TH
  round 0.254 hole 0.66 unplated: (-6.775,-0.7) (0.675,-0.7)
  rect 0.305x0.711 smd: A1(-5.8,1.11) A2(-5.3,1.11) A3(-4.8,1.11) A4(-4.3,1.11) A5(-3.8,1.11) A6(-3.3,1.11) A7(-2.8,1.11) A8(-2.3,1.11) A9(-1.8,1.11) A10(-1.3,1.11) A11(-0.8,1.11) A12(-0.3,1.11)
  round 0.66 hole 0.406: B1(0,0) B2(-0.65,-0.7) B3(-1.45,-0.7) B4(-1.85,0) B5(-2.25,-0.7) B6(-2.65,0) B7(-3.45,0) B8(-3.85,-0.7) B9(-4.25,0) B10(-4.65,-0.7) B11(-5.45,-0.7) B12(-6.1,0)
  oval 1.016x1.6 hole 0.508x1.118: SH1(-7.55,0.81) SH2(1.45,0.81)
  oval 1.016x1.803 hole 0.508x1.295: SH3(-7.55,-4.8) SH4(1.45,-4.8)
CON40_0P4_10P8X3P08_SM
  rect 0.203x0.711 smd: 1(-3.8,-1.54) 2(-3.8,1.54) 3(-3.4,-1.54) 4(-3.4,1.54) 5(-3,-1.54) 6(-3,1.54) 7(-2.6,-1.54) 8(-2.6,1.54) 9(-2.2,-1.54) 10(-2.2,1.54) 11(-1.8,-1.54) 12(-1.8,1.54) 13(-1.4,-1.54) 14(-1.4,1.54) 15(-1,-1.54) 16(-1,1.54) 17(-0.6,-1.54) 18(-0.6,1.54) 19(-0.2,-1.54) 20(-0.2,1.54) 21(0.2,-1.54) 22(0.2,1.54) 23(0.6,-1.54) 24(0.6,1.54) 25(1,-1.54) 26(1,1.54) 27(1.4,-1.54) 28(1.4,1.54) 29(1.8,-1.54) 30(1.8,1.54) 31(2.2,-1.54) 32(2.2,1.54) 33(2.6,-1.54) 34(2.6,1.54) 35(3,-1.54) 36(3,1.54) 37(3.4,-1.54) 38(3.4,1.54) 39(3.8,-1.54) 40(3.8,1.54)
CON100_0P4_22P8X3P1_SM
  rect 0.203x0.711 smd: 1(-9.8,-1.54) 2(-9.8,1.54) 3(-9.4,-1.54) 4(-9.4,1.54) 5(-9,-1.54) 6(-9,1.54) 7(-8.6,-1.54) 8(-8.6,1.54) 9(-8.2,-1.54) 10(-8.2,1.54) 11(-7.8,-1.54) 12(-7.8,1.54) 13(-7.4,-1.54) 14(-7.4,1.54) 15(-7,-1.54) 16(-7,1.54) 17(-6.6,-1.54) 18(-6.6,1.54) 19(-6.2,-1.54) 20(-6.2,1.54) 21(-5.8,-1.54) 22(-5.8,1.54) 23(-5.4,-1.54) 24(-5.4,1.54) 25(-5,-1.54) 26(-5,1.54) 27(-4.6,-1.54) 28(-4.6,1.54) 29(-4.2,-1.54) 30(-4.2,1.54) 31(-3.8,-1.54) 32(-3.8,1.54) 33(-3.4,-1.54) 34(-3.4,1.54) 35(-3,-1.54) 36(-3,1.54) 37(-2.6,-1.54) 38(-2.6,1.54) 39(-2.2,-1.54) 40(-2.2,1.54) 41(-1.8,-1.54) 42(-1.8,1.54) 43(-1.4,-1.54) 44(-1.4,1.54) 45(-1,-1.54) 46(-1,1.54) 47(-0.6,-1.54) 48(-0.6,1.54) 49(-0.2,-1.54) 50(-0.2,1.54) 51(0.2,-1.54) 52(0.2,1.54) 53(0.6,-1.54) 54(0.6,1.54) 55(1,-1.54) 56(1,1.54) 57(1.4,-1.54) 58(1.4,1.54) 59(1.8,-1.54) 60(1.8,1.54) 61(2.2,-1.54) 62(2.2,1.54) 63(2.6,-1.54) 64(2.6,1.54) 65(3,-1.54) 66(3,1.54) 67(3.4,-1.54) 68(3.4,1.54) 69(3.8,-1.54) 70(3.8,1.54) 71(4.2,-1.54) 72(4.2,1.54) 73(4.6,-1.54) 74(4.6,1.54) 75(5,-1.54) 76(5,1.54) 77(5.4,-1.54) 78(5.4,1.54) 79(5.8,-1.54) 80(5.8,1.54) 81(6.2,-1.54) 82(6.2,1.54) 83(6.6,-1.54) 84(6.6,1.54) 85(7,-1.54) 86(7,1.54) 87(7.4,-1.54) 88(7.4,1.54) 89(7.8,-1.54) 90(7.8,1.54) 91(8.2,-1.54) 92(8.2,1.54) 93(8.6,-1.54) 94(8.6,1.54) 95(9,-1.54) 96(9,1.54) 97(9.4,-1.54) 98(9.4,1.54) 99(9.8,-1.54) 100(9.8,1.54)
CON_2RH_10_50
  oval 1.067x1.676 hole 0.711: 1(0,0) 2(0,1.27) 3(1.27,0) 4(1.27,1.27) 5(2.54,0) 6(2.54,1.27) 7(3.81,0) 8(3.81,1.27) 9(5.08,0) 10(5.08,1.27)
CON_2X4_SKT_100_SM
  rect 2.235x1.016 smd: 1(2.826,3.81) 2(-2.826,3.81) 3(2.826,1.27) 4(-2.826,1.27) 5(2.826,-1.27) 6(-2.826,-1.27) 7(2.826,-3.81) 8(-2.826,-3.81)
CON_75_0P5_22X9_RA
  rect 1.194x2.743 smd: (-10.35,2.825) (10.35,2.825)
  round 0.254 hole 1.092 unplated: (-10,-1.675)
  round 0.254 hole 1.6 unplated: (10,-1.675)
  rect 0.305x1.549 smd: 1(-9.25,3.6) 2(-9,-3.95) 3(-8.75,3.6) 4(-8.5,-3.95) 5(-8.25,3.6) 6(-8,-3.95) 7(-7.75,3.6) 8(-7.5,-3.95) 9(-7.25,3.6) 10(-7,-3.95) 11(-6.75,3.6) 12(-6.5,-3.95) 13(-6.25,3.6) 14(-6,-3.95) 15(-5.75,3.6) 16(-5.5,-3.95) 17(-5.25,3.6) 18(-5,-3.95) 19(-4.75,3.6) 20(-4.5,-3.95) 21(-4.25,3.6) 22(-4,-3.95) 23(-3.75,3.6) 32(-1.5,-3.95) 33(-1.25,3.6) 34(-1,-3.95) 35(-0.75,3.6) 36(-0.5,-3.95) 37(-0.25,3.6) 38(0,-3.95) 39(0.25,3.6) 40(0.5,-3.95) 41(0.75,3.6) 42(1,-3.95) 43(1.25,3.6) 44(1.5,-3.95) 45(1.75,3.6) 46(2,-3.95) 47(2.25,3.6) 48(2.5,-3.95) 49(2.75,3.6) 50(3,-3.95) 51(3.25,3.6) 52(3.5,-3.95) 53(3.75,3.6) 54(4,-3.95) 55(4.25,3.6) 56(4.5,-3.95) 57(4.75,3.6) 58(5,-3.95) 59(5.25,3.6) 60(5.5,-3.95) 61(5.75,3.6) 62(6,-3.95) 63(6.25,3.6) 64(6.5,-3.95) 65(6.75,3.6) 66(7,-3.95) 67(7.25,3.6) 68(7.5,-3.95) 69(7.75,3.6) 70(8,-3.95) 71(8.25,3.6) 72(8.5,-3.95) 73(8.75,3.6) 74(9,-3.95) 75(9.25,3.6)
CON_DB_9F_109_TH_RA
  rect 1.727x1.727 hole 1.092: 1(0,0)
  round 1.727 hole 1.092: 2(-2.77,0) 3(-5.54,0) 4(-8.31,0) 5(-11.08,0) 6(-1.385,-2.84) 7(-4.155,-2.84) 8(-6.925,-2.84) 9(-9.695,-2.84)
  round 3.962 hole 3.2: M1(-18.035,-1.42) M2(6.955,-1.42)
CON_RA_HDMI_19P_0P5_SM_B
  rect 0.305x2.007 smd: 1(4.5,5.22) 2(4,5.22) 3(3.5,5.22) 4(3,5.22) 5(2.5,5.22) 6(2,5.22) 7(1.5,5.22) 8(1,5.22) 9(0.5,5.22) 10(0,5.22) 11(-0.5,5.22) 12(-1,5.22) 13(-1.5,5.22) 14(-2,5.22) 15(-2.5,5.22) 16(-3,5.22) 17(-3.5,5.22) 18(-4,5.22) 19(-4.5,5.22)
  oval 1.295x3.505 hole 0.711x2.896: G1(7.25,4.457) G2(-7.25,4.457)
  oval 1.295x2.489 hole 0.711x1.905: G3(7.25,-1.523) G4(-7.25,-1.523)
CON_RJ45_10_2LED_TH
  round 0.254 hole 3.251 unplated: (-11.43,8.89) (0,8.89)
  rect 1.499x1.499 hole 0.889: 1(0,0)
  round 1.499 hole 0.889: 2(-1.27,2.54) 3(-2.54,0) 4(-3.81,2.54) 5(-5.08,0) 6(-6.35,2.54) 7(-7.62,0) 8(-8.89,2.54) 9(-10.16,0) 10(-11.43,2.54)
  round 1.651 hole 1.016: 11(0.915,12.97) 12(-1.625,12.97) 13(-9.805,12.97) 14(-12.345,12.97)
  round 2.642 hole 1.6: SH1(2.03,5.84) SH2(-13.46,5.84)
CON_USB_TYPE_B_SM_A
  round 0.254 hole 0.66 unplated: (-2,2.15) (2,2.15)
  rect 0.406x1.346 smd: 1(-1.3,2.627) 2(-0.65,2.627) 3(0,2.627) 4(0.65,2.627) 5(1.3,2.627)
  oval 1.143x1.829 hole 0.508x1.194: S1(-3.2,-0.05) S2(3.2,-0.05)
  rect 1.6x1.219 smd: S3(-3.3,2.5) S4(3.3,2.5)
DFN3P3X3P3_8L_EX
  rect 0.559x0.356 smd: 1(-1.42,0.975) 2(-1.42,0.325) 3(-1.42,-0.325) 4(-1.42,-0.975)
  custom 0.57x0.57 smd: 5(0,0)
DFN15_0P4_2X3
  custom 0.051x0.051 smd: 1(-0.9,0.6)
  rect 1.194x0.203 smd: 2(-0.709,0.2) 3(-0.709,-0.6) 9(0.709,-0.2)
  rect 0.203x0.813 smd: 4(-0.6,-1.4) 5(-0.2,-1.4) 6(0.2,-1.4) 7(0.6,-1.4) 12(0.6,1.4) 13(0.2,1.4) 14(-0.2,1.4) 15(-0.6,1.4)
  rect 0.813x0.203 smd: 8(0.9,-0.6) 10(0.9,0.2) 11(0.9,0.6)
DIODE2_SOD523
  rect 0.61x0.813 smd: 1(-0.85,0) 2(0.85,0)
FUSE_3P4X1P8
  rect 0.991x1.803 smd: 1(-1.25,0) 2(1.25,0)
HDR102_TMM
  rect 1.499x1.499 hole 0.889: 1(0,0)
  round 1.499 hole 0.889: 2(-2,0)
HDR103
  rect 1.524x1.524 hole 1.016: 1(0,0)
  round 1.524 hole 1.016: 2(0,-2.54) 3(0,-5.08)
HDR104
  rect 1.676x1.676 hole 1.016: 1(0,0)
  round 1.676 hole 1.016: 2(0,-2.54) 3(0,-5.08) 4(0,-7.62)
HDR220_TSM_A_SM
  round 0.254 hole 1.727 unplated: (0,22.86) (0,-22.86)
  custom 0.318x0.318 smd: 1(-2.475,24.13) 2(2.475,24.13) 3(-2.475,21.59) 4(2.475,21.59) 37(-2.475,-21.59) 38(2.475,-21.59) 39(-2.475,-24.13) 40(2.475,-24.13)
  rect 3.683x1.27 smd: 5(-2.475,19.05) 6(2.475,19.05) 7(-2.475,16.51) 8(2.475,16.51) 9(-2.475,13.97) 10(2.475,13.97) 11(-2.475,11.43) 12(2.475,11.43) 13(-2.475,8.89) 14(2.475,8.89) 15(-2.475,6.35) 16(2.475,6.35) 17(-2.475,3.81) 18(2.475,3.81) 19(-2.475,1.27) 20(2.475,1.27) 21(-2.475,-1.27) 22(2.475,-1.27) 23(-2.475,-3.81) 24(2.475,-3.81) 25(-2.475,-6.35) 26(2.475,-6.35) 27(-2.475,-8.89) 28(2.475,-8.89) 29(-2.475,-11.43) 30(2.475,-11.43) 31(-2.475,-13.97) 32(2.475,-13.97) 33(-2.475,-16.51) 34(2.475,-16.51) 35(-2.475,-19.05) 36(2.475,-19.05)
HUQFN16_1P6X2P4
  rect 0.533x0.203 smd: 1(-0.767,1) 2(-0.767,0.6) 3(-0.767,0.2) 4(-0.767,-0.2) 5(-0.767,-0.6) 6(-0.767,-1) 9(0.767,-1) 10(0.767,-0.6) 11(0.767,-0.2) 12(0.767,0.2) 13(0.767,0.6) 14(0.767,1)
  rect 0.203x0.533 smd: 7(-0.2,-1.167) 8(0.2,-1.167) 15(0.2,1.167) 16(-0.2,1.167)
  rect 0.61x1.397 smd: 17(0,0)
HX2QFN16_0P4_2P7X2P7
  rect 0.813x0.203 smd: 1(-1.25,0.8) 2(-1.25,0.4) 3(-1.25,0) 4(-1.25,-0.4) 5(-1.25,-0.8) 9(1.25,-0.8) 10(1.25,-0.4) 11(1.25,0) 12(1.25,0.4) 13(1.25,0.8)
  rect 0.203x0.813 smd: 6(-0.4,-1.25) 7(0,-1.25) 8(0.4,-1.25) 14(0.4,1.25) 15(0,1.25) 16(-0.4,1.25)
  rect 1.194x1.092 smd: 17(0,0)
IND2_11P5X10P3_SM
  rect 4.089x4.089 smd: 1(0,-4.75) 2(0,4.75)
IND4_AMCW3225_SMT
  rect 1.041x1.041 smd: 1(-1.525,-0.725) 2(1.525,-0.725) 3(1.525,0.725) 4(-1.525,0.725)
IND_0402
  round 0.635 smd: 1(-0.508,0) 2(0.508,0)
IND_0603
  rect 0.991x0.813 smd: 1(-0.69,0) 2(0.69,0)
IND_IHLP
  rect 2.007x3.429 smd: 1(-2.794,0) 2(2.743,0)
IND_SPH2520
  rect 1.219x2.007 smd: 1(-1.01,0) 2(1.01,0)
LED_0603
  rect 0.838x0.787 smd: A(-0.775,0) C(0.775,0)
LED_0603_11MIL
  rect 0.838x0.787 smd: A(-0.775,0) C(0.775,0)
LQFP64_0P5_10X10
  rect 1.372x0.279 smd: 1(-5.775,3.75) 2(-5.775,3.25) 3(-5.775,2.75) 4(-5.775,2.25) 5(-5.775,1.75) 6(-5.775,1.25) 7(-5.775,0.75) 8(-5.775,0.25) 9(-5.775,-0.25) 10(-5.775,-0.75) 11(-5.775,-1.25) 12(-5.775,-1.75) 13(-5.775,-2.25) 14(-5.775,-2.75) 15(-5.775,-3.25) 16(-5.775,-3.75) 33(5.775,-3.75) 34(5.775,-3.25) 35(5.775,-2.75) 36(5.775,-2.25) 37(5.775,-1.75) 38(5.775,-1.25) 39(5.775,-0.75) 40(5.775,-0.25) 41(5.775,0.25) 42(5.775,0.75) 43(5.775,1.25) 44(5.775,1.75) 45(5.775,2.25) 46(5.775,2.75) 47(5.775,3.25) 48(5.775,3.75)
  rect 0.279x1.372 smd: 17(-3.75,-5.775) 18(-3.25,-5.775) 19(-2.75,-5.775) 20(-2.25,-5.775) 21(-1.75,-5.775) 22(-1.25,-5.775) 23(-0.75,-5.775) 24(-0.25,-5.775) 25(0.25,-5.775) 26(0.75,-5.775) 27(1.25,-5.775) 28(1.75,-5.775) 29(2.25,-5.775) 30(2.75,-5.775) 31(3.25,-5.775) 32(3.75,-5.775) 49(3.75,5.775) 50(3.25,5.775) 51(2.75,5.775) 52(2.25,5.775) 53(1.75,5.775) 54(1.25,5.775) 55(0.75,5.775) 56(0.25,5.775) 57(-0.25,5.775) 58(-0.75,5.775) 59(-1.25,5.775) 60(-1.75,5.775) 61(-2.25,5.775) 62(-2.75,5.775) 63(-3.25,5.775) 64(-3.75,5.775)
MH244-166T
  round 6.477 hole 4.318: 1(0,0)
PQFN16_0P4_2P65X1P85
  rect 0.203x0.762 smd: 1(-0.6,-0.724)
  rect 0.203x0.66 smd: 2(-0.2,-0.775) 3(0.2,-0.775) 4(0.6,-0.775) 9(0.6,0.775) 10(0.2,0.775) 11(-0.2,0.775) 12(-0.6,0.775)
  rect 0.66x0.203 smd: 5(1.21,-0.6) 6(1.21,-0.2) 7(1.21,0.2) 8(1.21,0.6) 13(-1.21,0.6) 14(-1.21,0.2) 15(-1.21,-0.2) 16(-1.21,-0.6)
QFN12_0P5_2X3MM_EP
  rect 0.711x0.254 smd: 1(-0.95,0.5) 2(-0.95,0) 3(-0.95,-0.5) 7(0.95,-0.5) 8(0.95,0) 9(0.95,0.5)
  rect 0.254x0.914 smd: 4(-0.5,-1.35) 5(0,-1.35) 6(0.5,-1.35)
  custom 0.225x0.225 smd: 10(0,1.35)
  rect 0.406x0.254 smd: 11(0,0)
QFN12_0P5_3P1X2P1
  rect 0.254x1.499 smd: 1(0.5,0.55) 2(-0.5,0.55) 7(0,-0.55)
  rect 0.711x0.254 smd: 3(-1.45,0.75) 4(-1.45,0.25) 5(-1.45,-0.25) 6(-1.45,-0.75) 9(1.45,-0.75) 10(1.45,-0.25) 11(1.45,0.25) 12(1.45,0.75)
  rect 0.254x0.711 smd: 8(0.5,-0.95)
QFN24_0P5_4X4_EP2P2
  oval 0.813x0.279 smd: 1(-1.86,1.25) 2(-1.86,0.75) 3(-1.86,0.25) 4(-1.86,-0.25) 5(-1.86,-0.75) 6(-1.86,-1.25) 13(1.86,-1.25) 14(1.86,-0.75) 15(1.86,-0.25) 16(1.86,0.25) 17(1.86,0.75) 18(1.86,1.25)
  oval 0.279x0.813 smd: 7(-1.25,-1.86) 8(-0.75,-1.86) 9(-0.25,-1.86) 10(0.25,-1.86) 11(0.75,-1.86) 12(1.25,-1.86) 19(1.25,1.86) 20(0.75,1.86) 21(0.25,1.86) 22(-0.25,1.86) 23(-0.75,1.86) 24(-1.25,1.86)
  rect 2.438x2.438 smd: 25(0,0)
QFN24_0P5_5P6X3P6_EP
  rect 0.305x0.914 smd: 1(-0.75,2.8) 12(-0.75,-2.8) 13(0.75,-2.8) 24(0.75,2.8)
  rect 0.914x0.305 smd: 2(-1.8,2.25) 3(-1.8,1.75) 4(-1.8,1.25) 5(-1.8,0.75) 6(-1.8,0.25) 7(-1.8,-0.25) 8(-1.8,-0.75) 9(-1.8,-1.25) 10(-1.8,-1.75) 11(-1.8,-2.25) 14(1.8,-2.25) 15(1.8,-1.75) 16(1.8,-1.25) 17(1.8,-0.75) 18(1.8,-0.25) 19(1.8,0.25) 20(1.8,0.75) 21(1.8,1.25) 22(1.8,1.75) 23(1.8,2.25)
  rect 2.235x4.242 smd: 25(0,0)
QFN24_4X4_EP2P25MM
  oval 0.279x0.813 smd: 1(-1.25,-1.956) 2(-0.75,-1.956) 3(-0.25,-1.956) 4(0.25,-1.956) 5(0.75,-1.956) 6(1.25,-1.956) 13(1.25,1.956) 14(0.75,1.956) 15(0.25,1.956) 16(-0.25,1.956) 17(-0.75,1.956) 18(-1.25,1.956)
  oval 0.813x0.279 smd: 7(1.956,-1.25) 8(1.956,-0.75) 9(1.956,-0.25) 10(1.956,0.25) 11(1.956,0.75) 12(1.956,1.25) 19(-1.956,1.25) 20(-1.956,0.75) 21(-1.956,0.25) 22(-1.956,-0.25) 23(-1.956,-0.75) 24(-1.956,-1.25)
  rect 2.235x2.235 smd: 25(0,0)
QFN32_S142EP
  custom 0.07x0.07 smd: 1(-2.4,1.751) 2(-2.4,1.251) 3(-2.4,0.751) 4(-2.4,0.25) 5(-2.4,-0.25) 6(-2.4,-0.751) 7(-2.4,-1.251) 8(-2.4,-1.751) 9(-1.751,-2.4) 10(-1.251,-2.4) 11(-0.751,-2.4) 12(-0.25,-2.4) 13(0.25,-2.4) 14(0.751,-2.4) 15(1.251,-2.4) 16(1.751,-2.4) 17(2.4,-1.751) 18(2.4,-1.251) 19(2.4,-0.751) 20(2.4,-0.25) 21(2.4,0.25) 22(2.4,0.751) 23(2.4,1.251) 24(2.4,1.751) 25(1.751,2.4) 26(1.251,2.4) 27(0.751,2.4) 28(0.25,2.4) 29(-0.25,2.4) 30(-0.751,2.4) 31(-1.251,2.4) 32(-1.751,2.4)
  rect 3.607x3.607 smd: 33(0,0)
QFN40_0P4_5X5MM
  oval 0.813x0.203 smd: 1(-2.46,1.8) 10(-2.46,-1.8) 21(2.46,-1.8) 30(2.46,1.8)
  rect 0.813x0.203 smd: 2(-2.46,1.4) 3(-2.46,1) 4(-2.46,0.6) 5(-2.46,0.2) 6(-2.46,-0.2) 7(-2.46,-0.6) 8(-2.46,-1) 9(-2.46,-1.4) 22(2.46,-1.4) 23(2.46,-1) 24(2.46,-0.6) 25(2.46,-0.2) 26(2.46,0.2) 27(2.46,0.6) 28(2.46,1) 29(2.46,1.4)
  oval 0.203x0.813 smd: 11(-1.8,-2.46) 20(1.8,-2.46) 31(1.8,2.46) 40(-1.8,2.46)
  rect 0.203x0.813 smd: 12(-1.4,-2.46) 13(-1,-2.46) 14(-0.6,-2.46) 15(-0.2,-2.46) 16(0.2,-2.46) 17(0.6,-2.46) 18(1,-2.46) 19(1.4,-2.46) 32(1.4,2.46) 33(1,2.46) 34(0.6,2.46) 35(0.2,2.46) 36(-0.2,2.46) 37(-0.6,2.46) 38(-1,2.46) 39(-1.4,2.46)
  rect 3.607x3.607 smd: 41(0,0)
RC0402_25
  round 0.635 smd: 1(-0.508,0) 2(0.508,0)
RC0805_OV
  oval 0.889x1.524 smd: 1(-0.965,0) 2(0.965,0)
SC70_3
  rect 0.711x0.889 smd: 1(-0.648,-0.952) 2(0.648,-0.952) 3(0,0.952)
SOD123LF
  rect 1.219x1.27 smd: A(1.549,0) C(-1.549,0)
SOD323
  rect 0.889x1.219 smd: A(0,1.27) C(0,-1.27)
SOD523
  rect 0.61x0.813 smd: A(0.85,0) C(-0.85,0)
SOIC14_1P27_4X8
  rect 1.448x0.61 smd: 1(-2.726,3.81) 2(-2.726,2.54) 3(-2.726,1.27) 4(-2.726,0) 5(-2.726,-1.27) 6(-2.726,-2.54) 7(-2.726,-3.81) 8(2.726,-3.81) 9(2.726,-2.54) 10(2.726,-1.27) 11(2.726,0) 12(2.726,1.27) 13(2.726,2.54) 14(2.726,3.81)
SOT23-5
  rect 0.61x1.118 smd: 1(-1,-1.4) 2(-0.05,-1.4) 3(0.9,-1.4) 4(0.9,1.45) 5(-1,1.45)
SOT23_A
  rect 0.787x0.889 smd: 1(-0.94,-1.003) 2(0.94,-1.003) 3(0,1.003)
SOT-23
  rect 1.016x1.397 smd: 1(-0.95,-1.1) 2(0.95,-1.1) 3(0,1.1)
SOT-23-5
  rect 0.686x0.991 smd: 1(-0.953,-1.295) 2(0,-1.295) 3(0.953,-1.295) 4(0.953,1.295) 5(-0.953,1.295)
SPACER_139T
  round 5.588 hole 3.531: 1(0,0)
STANDOFF_CIRCLE_5P1-2P5MM_NSP
  round 5.994 hole 3.708: 1(0,0)
SW4_PB_ESW_SM_P177
  rect 1.397x2.794 smd: 1(2.248,4.547) 2(2.248,-4.547) 3(-2.248,4.547) 4(-2.248,-4.547)
SW6_DPDT_M096H_TH
  rect 1.346x1.346 hole 0.711: 1(0,0)
  round 1.346 hole 0.711: 2(0,-2.5) 3(0,-5) 4(3.2,0) 5(3.2,-2.5) 6(3.2,-5)
TEST_PIN_TP107
  rect 4.699x3.429 smd: 1(0,0)
TESTPOINT_35MIL
  round 0.889 smd: 1(0,0)
TPAD_020
  round 0.508 smd: 1(0,0)
TPAD_050
  round 1.27 smd: 1(0,0)
TSSOP8
  rect 1.778x0.356 smd: 1(-2.819,0.975) 2(-2.819,0.325) 3(-2.819,-0.325) 4(-2.819,-0.975) 5(2.819,-0.975) 6(2.819,-0.325) 7(2.819,0.325) 8(2.819,0.975)
TSSOP8_A
  rect 1.448x0.457 smd: 1(-2.15,0.975) 2(-2.15,0.325) 3(-2.15,-0.325) 4(-2.15,-0.975) 5(2.15,-0.975) 6(2.15,-0.325) 7(2.15,0.325) 8(2.15,0.975)
UDFN6_1X1P5MM
  rect 0.584x0.305 smd: 1(-0.418,0.5)
  rect 0.508x0.305 smd: 2(-0.38,0) 3(-0.38,-0.5) 4(0.38,-0.5) 5(0.38,0) 6(0.38,0.5)
WDFN12_0P5_3X1MM
  rect 0.533x0.305 smd: 1(-0.365,1.25) 2(-0.365,0.75) 3(-0.365,0.25) 4(-0.365,-0.25) 5(-0.365,-0.75) 6(-0.365,-1.25) 7(0.365,-1.25) 8(0.365,-0.75) 9(0.365,-0.25) 10(0.365,0.25) 11(0.365,0.75) 12(0.365,1.25)
WLCSP5_0P4_0P82X1P22
  round 0.254 smd: A1(-0.2,0.4) A2(0.2,0.4) B1(0,0) C1(-0.2,-0.4) C2(0.2,-0.4)
WLCSP10_0P4_1P2X1P6MM_SMDP
  round 0.254 smd: A1(0.4,0.6) A2(0.4,0.2) A3(0.4,-0.2) A4(0.4,-0.6) B1(0,0.4) B2(0,-0.4) C1(-0.4,0.6) C2(-0.4,0.2) C3(-0.4,-0.2) C4(-0.4,-0.6)
WLCSP12_0P4_1P3X1P7MM_SMDP
  round 0.254 smd: A1(-0.4,0.6) A2(0,0.6) A3(0.4,0.6) B1(-0.4,0.2) B2(0,0.2) B3(0.4,0.2) C1(-0.4,-0.2) C2(0,-0.2) C3(0.4,-0.2) D1(-0.4,-0.6) D2(0,-0.6) D3(0.4,-0.6)
WLCSP15_0P5_1P57X2P59
  round 0.254 smd: A1(0.5,1) A2(0,1) A3(-0.5,1) B1(0.5,0.5) B2(0,0.5) B3(-0.5,0.5) C1(0.5,0) C2(0,0) C3(-0.5,0) D1(0.5,-0.5) D2(0,-0.5) D3(-0.5,-0.5) E1(0.5,-1) E2(0,-1) E3(-0.5,-1)
WLCSP42_0P4_2P94X2P54_SMDP
  round 0.254 smd: A1(-1,1.2) A2(-0.6,1.2) A3(-0.2,1.2) A4(0.2,1.2) A5(0.6,1.2) A6(1,1.2) B1(-1,0.8) B2(-0.6,0.8) B3(-0.2,0.8) B4(0.2,0.8) B5(0.6,0.8) B6(1,0.8) C1(-1,0.4) C2(-0.6,0.4) C3(-0.2,0.4) C4(0.2,0.4) C5(0.6,0.4) C6(1,0.4) D1(-1,0) D2(-0.6,0) D3(-0.2,0) D4(0.2,0) D5(0.6,0) D6(1,0) E1(-1,-0.4) E2(-0.6,-0.4) E3(-0.2,-0.4) E4(0.2,-0.4) E5(0.6,-0.4) E6(1,-0.4) F1(-1,-0.8) F2(-0.6,-0.8) F3(-0.2,-0.8) F4(0.2,-0.8) F5(0.6,-0.8) F6(1,-0.8) G1(-1,-1.2) G2(-0.6,-1.2) G3(-0.2,-1.2) G4(0.2,-1.2) G5(0.6,-1.2) G6(1,-1.2)
XQFN12_0P4_1P8X2P1
  rect 0.66x0.305 smd: 1(-0.675,0.85)
  rect 0.66x0.203 smd: 2(-0.675,0.4) 3(-0.675,0) 4(-0.675,-0.4) 5(-0.675,-0.8) 7(0.675,-0.8) 8(0.675,-0.4) 9(0.675,0) 10(0.675,0.4) 11(0.675,0.8)
  rect 0.203x0.66 smd: 6(0,-0.825) 12(0,0.825)
XQFN16_0P4_2P7X1P9
  rect 0.203x0.965 smd: 1(-0.6,-0.625) 2(-0.2,-0.625) 3(0.2,-0.625) 4(0.6,-0.625) 9(0.6,0.625) 10(0.2,0.625) 11(-0.2,0.625) 12(-0.6,0.625)
  rect 0.66x0.203 smd: 5(1.21,-0.6) 6(1.21,-0.2) 7(1.21,0.2) 8(1.21,0.6) 13(-1.21,0.6) 14(-1.21,0.2) 15(-1.21,-0.2) 16(-1.21,-0.6)
XSON10_0P5_1P1X2P6MM
  rect 0.711x0.254 smd: 1(-0.457,1) 2(-0.457,0.5) 3(-0.457,0) 4(-0.457,-0.5) 5(-0.457,-1) 6(0.457,-1) 7(0.457,-0.5) 8(0.457,0) 9(0.457,0.5) 10(0.457,1)
XTAL_4_3P3X2P6MM
  rect 1.397x1.194 smd: 1(-1.1,-0.85) 2(1.1,-0.85) 3(1.1,0.85) 4(-1.1,0.85)
XTLOSC4_2P5X2MM_SM
  rect 0.889x0.813 smd: 1(-0.826,-0.635) 2(0.826,-0.635) 3(0.826,0.635) 4(-0.826,0.635)

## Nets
5V_PG: TP69.1(TP) U63.3
GND: BH1.1 BH2.1 BH3.1 BH4.1 BH5.1(NC_1) BH6.1(NC_1) BH7.1(NC_1) BH8.1(NC_1) BH9.1 BH10.1 BH11.1 BH12.1 C1.2 C2.2 C3.2 C4.2 C5.2 C6.2 C7.2 C8.2 C9.2 C10.2 C11.2 C12.2 C13.2 C14.2 C15.2 C16.2 C17.2 C18.2 C19.2 C20.2 C21.2 C22.2 C23.2 C24.2 C25.2 C26.2 C27.2 C29.1 C30.2 C31.1 C32.2 C33.2 C34.2 C35.2 C36.2 C37.2 C40.2 C41.2 C42.2 C44.2 C45.2 C46.2 C47.2 C51.1 C54.2 C55.2 C56.2 C57.1 C61.1 C62.2 C64.2 C65.2 C66.2 C67.2 C68.2 C69.2 C70.2 C71.2 C72.2 C73.2 C74.2 C75.2 C76.2 C77.2 C78.1 C79.2 C80.2 C81.2 C82.2 C83.2 C84.2 C85.2 C86.2 C87.2 C88.2 C89.2 C90.2 C91.2 C92.2 C93.2 C94.2 C95.2 C96.2 C97.2 C98.2 C99.2 C100.2 C101.2 C102.2 C103.2 C104.2 C105.2 C106.2 C107.2 C108.2 C109.2 C110.2 C111.2 C112.2 C113.2 C114.2 C115.2 C116.2 C117.2 C118.2 C119.2 C123.2 C124.2 C125.2 C126.2 C127.2 C128.2 C129.2 C130.2 C131.2 C132.2 C133.2 C134.2 C135.2 C136.2 C137.2 C138.2 C139.2 C140.2 C141.2 C142.2 C143.2 C144.2 C145.2 C146.2 C147.2 C148.2 C149.2 C150.2 C151.2 C152.2 C153.2 C154.2 C155.2 C156.2 C157.2 C158.2 C163.2 C164.2 C168.2 C169.2 C170.2 C171.2 C174.2 C175.2 C176.1 C179.2 C181.1 C182.2 C184.2 C185.2 C186.2 C187.2 C188.2 C189.2 C190.2 C192.2 C193.2 C194.1 C196.2 C198.1 C200.2 C201.2 C202.2 C203.2 C204.2 C205.2 C206.1 C207.2 C208.2 C214.1 C215.2 C216.2 C217.2 C218.1 C219.2 C220.1 C223.1 C224.2 C226.2 C228.2 C229.2 C230.2 C231.2 C232.2 C233.2 C234.2 C235.2 C236.2 C237.2 C238.2 C239.2 C240.2 C241.2 C242.2 C243.2 C244.2 C245.2 C246.2 C251.2 C252.2 C253.2 C255.2 C257.2 C258.2 C259.2 C260.2 C263.2 C265.2 C266.2 C267.2 C269.2 C270.2 C271.2 C273.2 C274.2 C275.2 C277.2 C279.2 C281.2 C282.2 C283.1 C286.2 C287.2 C288.2 C289.2 C294.2 C295.2 C296.2 C297.2 C298.2 C299.2 C300.2 C305.2 C306.1 C307.2 C308.1 C309.2 C310.1 C317.2 C318.2 C319.2 C320.2 C321.2 C322.1 C324.2 C325.2 C326.2 C327.2 C328.2 C329.2 C330.2 C331.2 C332.1 C333.2 C334.2 C335.2 C336.2 C337.2 C338.2 C339.2 C342.2 C343.2 C345.2 C346.2 C348.2 C349.2 D10.2(A2) D11.2(A2) D12.2(A2) D13.2(A2) D14.3(COM_CATHODE) D15.3(COM_CATHODE) D24.A D25.C(CATHODE) J1.7 J1.8 J1.14 J1.17 J1.24 J1.27 J1.33 J1.34 J1.39 J1.40 J1.45 J1.46 J1.51 J1.52 J1.57 J1.58 J1.63 J1.69 J1.70 J1.75 J1.76 J1.81 J1.82 J1.87 J1.88 J1.93 J1.94 J1.99 J1.100 J2.1 J2.2 J2.7 J2.8 J2.13 J2.14 J2.19 J2.20 J2.25 J2.26 J2.31 J2.32 J2.37 J2.40 J2.43 J2.49 J2.50 J2.55 J2.60 J2.61 J2.69 J2.70 J2.79 J2.80 J2.84 J2.88 J2.89 J2.92 J2.96 J2.99 J2.100 J3.13 J3.14 J3.15 J3.16 J3.17 J3.18 J3.19 J3.20 J3.21 J3.22 J3.23 J3.24 J3.25 J3.26 J3.27 J3.28 J3.49 J3.50 J3.59 J3.60 J3.69 J3.70 J3.79 J3.80 J3.89 J3.90 J3.99 J3.100 J4.9 J4.10 J4.19 J4.20 J4.29 J4.30 J4.39 J4.40 J4.45 J4.50 J4.51 J4.57 J4.60 J4.63 J4.69 J4.70 J4.75 J4.80 J4.81 J4.89 J4.90 J4.99 J4.100 J5.A1 J5.A12 J5.B1 J5.B12 J5.SH1 J5.SH2 J5.SH3 J5.SH4 J6.A1 J6.A12 J6.B1 J6.B12 J6.SH1 J6.SH2 J6.SH3 J6.SH4 J7.4 J7.7 J7.S1 J7.S2 J8.10 J9.10 J10.1 J10.7 J10.18 J10.33 J10.39 J10.45 J10.51 J10.57 J10.63 J10.69 J10.75 J11.6(VSS) J11.10 J11.11 J11.12 J11.13 J12.1 J12.2 J12.3 J12.4 J12.5 J12.6(SH6) J12.A1 J12.A4 J12.A7 J12.A12 J12.A15 J12.A18 J12.B1 J12.B4 J12.B7 J12.B12 J12.B15 J12.B18 J13.1 J13.2 J13.3 J13.4 J13.5 J13.6(SH6) J13.A1 J13.A4 J13.A7 J13.A12 J13.A15 J13.A18 J13.B1 J13.B4 J13.B7 J13.B12 J13.B15 J13.B18 J14.1 J14.2 J14.3 J14.4 J14.5 J14.6(SH6) J14.A1 J14.A4 J14.A7 J14.A12 J14.A15 J14.A18 J14.B1 J14.B4 J14.B7 J14.B12 J14.B15 J14.B18 J15.1 J15.2 J15.3 J15.4 J15.5 J15.6(SH6) J15.A1 J15.A4 J15.A7 J15.A12 J15.A15 J15.A18 J15.B1 J15.B4 J15.B7 J15.B12 J15.B15 J15.B18 J16.1 J16.2 J16.3 J16.4 J16.5 J16.6(SH6) J16.A1 J16.A4 J16.A7 J16.A12 J16.A15 J16.A18 J16.B1 J16.B4 J16.B7 J16.B12 J16.B15 J16.B18 J17.2 J17.5 J17.8 J17.11 J17.17 J17.G1 J17.G2 J17.G3 J17.G4 J18.2 J19.3 J19.5 J19.6 J20.3 J20.5 J20.6 J21.6 J21.9 J21.14 J21.20 J21.25 J21.30 J21.34 J21.39 J22.7 J22.8(B4) J23.5 J23.S1 J23.S2 J23.S3 J23.S4 J24.3 J24.5 J25.2 J25.4 J25.6 J25.8 J25.10 J25.12 J25.19 J25.20 J25.29 J25.30 J25.39 J25.40 J26.3 J27.2 Q1.2(SOURCE) Q2.2(SOURCE) Q7.2(SOURCE) Q10.2(SOURCE) Q11.2(SOURCE) Q12.2(SOURCE) Q13.2(SOURCE) Q15.2(SOURCE) Q17.2(SOURCE) R5.2 R34.2 R38.2 R44.2 R45.2 R49.1 R51.2 R52.2 R56.1 R57.1 R65.2 R67.1 R74.2 R78.2 R81.2 R82.1 R92.2 R93.2 R94.2 R95.2 R96.2 R97.2 R98.2 R99.2 R104.2 R109.2 R112.2 R119.2 R121.2 R122.2 R123.2 R124.2 R125.2 R126.2 R128.2 R141.1 R148.1 R176.2 R190.1 R196.2 R209.2 R217.1 R218.1 R247.2 R248.2 R259.2 R260.2 R266.2 R272.2 R273.2 R278.2 R280.2 R287.2 R288.2 R289.2 R290.2 R322.1 R323.1 R330.2 R347.2 R351.2 R383.1 R409.1 R427.2 R430.1 R438.2 R443.1 R444.2 R445.2 R446.2 R450.2 R453.2 R457.2 SW1.1 SW1.2 SW2.1 SW2.2 TP72.1(PIN1) TP73.1(PIN1) TP74.1(PIN1) TP75.1(PIN1) TP76.1(PIN1) TP77.1(PIN1) TP78.1(PIN1) TP79.1(PIN1) TP80.1(PIN1) TP111.1(TP) TP112.1(TP) TP113.1(TP) TP114.1(TP) TP115.1(TP) TP124.1(PIN1) TVS1.1 TVS2.1 TVS3.1 TVS4.1 TVS5.1 TVS6.1 TVS7.1 TVS8.1 U1.9(VSS) U1.18 U1.25 U2.1 U2.3 U3.11 U3.12 U3.13 U3.22 U3.25 U4.10 U4.11 U5.6 U6.6 U7.6 U8.6 U9.C3 U9.D3 U9.E3 U10.B3 U10.D3 U11.5 U11.17 U12.2(V-) U13.2 U14.A4 U14.B2 U14.B3 U14.B4 U14.B5 U15.B3 U15.D3 U16.B1 U16.B2(GND_CH2) U17.5 U17.17 U18.11 U18.17 U19.B1 U19.B2(GND_CH2) U20.6 U21.B1 U21.B2(GND_CH2) U22.B3 U22.C3 U22.D3 U23.41 U24.3 U24.8 U25.3 U25.8 U26.41 U27.3 U27.8 U28.3 U28.8 U29.6 U29.10 U29.15 U29.21 U29.24 U29.25 U30.B1(GND) U31.3 U31.8 U32.3 U32.8 U33.3 U33.8 U34.3 U34.8 U35.3 U35.8 U36.3 U36.8 U37.3 U37.8 U38.3 U38.8 U39.3 U39.8 U40.3 U40.8 U41.3 U41.8 U42.3 U42.8 U43.3 U43.8 U44.3 U44.8 U45.3 U45.8 U46.B1 U46.B2(GND_CH2) U47.B1 U47.B2(GND_CH2) U48.4 U49.3 U49.8 U49.12 U50.9 U50.20 U50.24 U50.28 U50.33 U51.2 U51.5 U52.3 U52.6 U53.10 U53.11 U54.3 U54.6 U55.6 U56.6 U57.6 U58.6 U59.2 U60.1 U60.5 U60.10 U60.11 U60.13 U60.15 U60.25 U60.35 U60.47 U60.51 U61.10 U61.11 U62.B1(GND) U63.2 U63.10 U64.10 U66.3 U67.3 U70.9(VSS) U70.18 U70.25 U71.1 U74.2 U75.B1(GND) U77.B1(GND) U78.3 U79.1 U79.3 U80.4 U81.1 U81.3 X1.2 X1.4 Y1.2 Y1.4 Y2.2 Y2.4 Y3.2 Y3.4
GND_CHASSIS: C78.2 J8.SH1 J8.SH2 J9.SH1 J9.SH2 J19.M1 J19.M2 J20.M1 J20.M2 R82.2
VBUS_DBG: J23.1(VBUS) L15.1 TVS7.2(A2)
VBUS_IN: C25.1 C26.1 C40.1 C255.1 C279.1 R53.2 R54.2 R252.1 TP102.1(PIN1) U9.A1 U9.B1 U9.C1 U9.D1 U49.2(VIN) U63.1
VBUS_USB_DBG: C236.1 C237.1 C238.1 J25.7 J25.9 J25.11 L15.2 U59.1 U59.3
VCC_3V6: C263.1 R258.1 U63.9
VCC_FT_1V8: C298.1 C299.1 C300.1 C305.1 C306.2 C319.1 C320.1 C327.1 C335.1 L23.2 L24.1 R410.1 R415.1 R416.1 R417.1 R418.1 R419.1 R420.1 R421.1 TP127.1(TP) U7.11 U60.12 U60.37 U60.64 U66.6 U67.6 U70.21
VCC_FT_3V3: C239.1 C243.1 C244.1 C245.1 C246.1 C296.1 C297.1 C307.1 C308.2 C317.1 C318.1 C324.1 C330.1 C331.1 C338.1 L21.1 L22.1 R235.2 R236.1 R237.2 R240.1 R241.2 R242.2 R329.1 R333.1 R334.1 R385.1 R411.1 R413.1 R440.2 TP126.1(TP) U7.1 U59.5(VOUT) U60.20 U60.31 U60.42 U60.50 U60.56 U61.2(VCCB) U70.23 U74.1 U74.3 U80.8
VDD_1V8: C1.1 C2.1 C5.1 C6.1 C7.1 C10.1 C12.1 C21.1 C22.1 C23.1 C33.1 C37.1 C55.1 C56.1 C125.1 C126.1 C131.1 C132.1 C137.1 C138.1 C143.1 C147.1 C148.1 C152.1 C168.1 C169.1 C184.1 C185.1 C186.1 C217.1 C218.2 C228.1 C230.1 C232.1 C234.1 C286.1 C287.1 C309.1 C310.2 C321.1 C322.2 C328.1 C329.1 C336.1 C337.1 C345.1 C346.1 D22.A J3.29 J3.31 J3.33 J3.35 J3.37 J3.39 J12.A5 J12.A6 J13.A5 J13.A6 J14.A5 J14.A6 J15.A5 J15.A6 J16.A5 J16.A6 L9.2 L10.1 Q5.1 R4.1 R7.1 R8.1 R9.1 R10.1 R15.1 R16.1 R17.1 R18.1 R19.1 R27.1 R41.1 R43.2 R70.1 R101.1 R130.1 R147.1 R177.1 R178.1 R186.1 R216.1 R223.1 R224.1 R225.1 R226.1 R243.1 R244.1 R246.1 R283.2 R284.2 R285.2 R286.2 R312.1 R313.2 R422.2 R423.2 R429.1 R431.1 TP123.1(PIN1) TP132.1(TP) U1.23 U2.6 U3.1 U4.3 U5.1 U6.1 U8.14(VDD) U18.4 U20.14(VDD) U48.1 U50.8 U50.10 U52.9 U52.12(VCC2) U53.3 U54.9 U54.12(VCC2) U55.1 U56.1 U57.1 U58.1 U61.3 U78.6 U79.6
VDD_3V3: C3.1 C4.1 C8.1 C9.1 C11.1 C13.1 C18.1 C19.1 C20.1 C30.1 C54.1 C204.1 C205.1 C219.1 C220.2 C288.1 C289.1 D9.A J3.30 J3.32 J3.34 J3.36 J3.38 J3.40 L1.1 L2.1 L5.1 L6.1 L14.1 R11.1 R12.1 R13.1 R14.1 R20.1 R21.1 R22.1 R23.1 R48.1 R60.1 R66.1 R68.1 R83.2 R84.2 R113.2 R114.2 R129.1 R212.1 R264.1 R269.1 R270.1 R282.1 R426.1 R447.2 R448.1 TP131.1(TP) U1.21 U3.23 U3.24(VCCB2) U4.2(VCCB) U5.11(VCCB) U6.11(VCCB) U11.3(VDD) U17.3(VDD) U51.11(VIO) U53.2(VCCB)
VDD_3V3_CN: D9.C(CATHODE) R174.1
VDD_5V: C31.2 C32.1 C57.2 C129.1 C130.1 C135.1 C136.1 C141.1 C142.1 C145.1 C150.1 C154.1 C156.1 C197.1 C202.1 C203.1 C261.1 C266.1 C267.1 J12.A16 J12.A17 J13.A16 J13.A17 J14.A16 J14.A17 J15.A16 J15.A17 J16.A16 J16.A17 L26.1 Q6.2(SOURCE) Q8.5 Q16.2(SOURCE) R46.1 R204.1 R455.1 TP68.1(PIN1) U11.12 U12.5 U17.12 U51.3
1GB_LINK/ACTIVE: J8.11 R78.1
10M_100M_LINK/ACTIVE: J8.13 R74.1
AUD_3V3: C189.1 C190.1 L14.2 R187.1 U50.32
AUD_5V: C15.1 C187.1 C188.1 Q6.3 U50.21 U50.26
AUD_NINT: J4.26 R188.1
AUD_PWR_EN: J4.24 R207.1
AUD_SCL: R198.2 U50.17
AUD_SDA: R197.2 U50.18
BOOT_MODE0: J1.9 U20.2
BOOT_MODE1: J1.11 U20.5
BOOT_MODE2: J1.13 U20.7
BOOT_MODE3: J1.15 U20.10
BYPASS: C29.2 U11.4
BYPASS1: C51.2 U17.4
CAN1/I2C5_SEL: R444.1 U1.3 U52.7 U52.10
CAN1_H: C206.2 D14.2 J19.7 L19.2 R210.1
CAN1_L: C208.1 D14.1 J19.2 L19.3 R211.1
CAN1_RX: TP108.1(TP) U52.5 U53.8
CAN1_RX_3V3: U51.4 U53.13
CAN1_STBY_3V3: R212.2 U3.15 U51.14
CAN1_TX: TP106.1(TP) U52.2 U53.6
CAN1_TX_3V3: U51.1 U53.15
CAN1H: L19.1 U51.13
CAN1L: L19.4 U51.12
CAN2_H: C214.2 D15.2 J20.7 L20.2 R214.1
CAN2_L: C216.1 D15.1 J20.2 L20.3 R215.1
CAN2_RX: J4.8 TP109.1(TP) U53.9
CAN2_RX_3V3: U51.7 U53.12
CAN2_STBY_3V3: R426.2 U3.14 U51.8
CAN2_TX: TP107.1(TP) U53.7 U54.11
CAN2_TX_3V3: U51.6 U53.14
CAN2H: L20.1 U51.10
CAN2L: L20.4 U51.9
CLK_PD#: TP128.1(PIN1) U29.22
CLKIN1: J2.86 TP1.1(TP)
CLKIN2: J2.94 TP3.1(TP)
CLKOUT1: J2.90 TP2.1(TP)
CLKOUT2: J2.98 TP4.1(TP)
CON_JTAG_TCK: J24.4 U8.16
CON_JTAG_TDI: J24.8 R244.2 U8.3
CON_JTAG_TDO: J24.6 U8.12
CON_JTAG_TMS: J24.2 R243.2 U8.9
CSI1_CKN: J1.84 J12.A2 U31.1 U31.10(NC4)
CSI1_CKP: J1.86 J12.A3 U31.2 U31.9
CSI1_DN0: J1.72 J12.B2 U32.1 U32.10(NC4)
CSI1_DN1: J1.78 J12.B5 U32.4 U32.7
